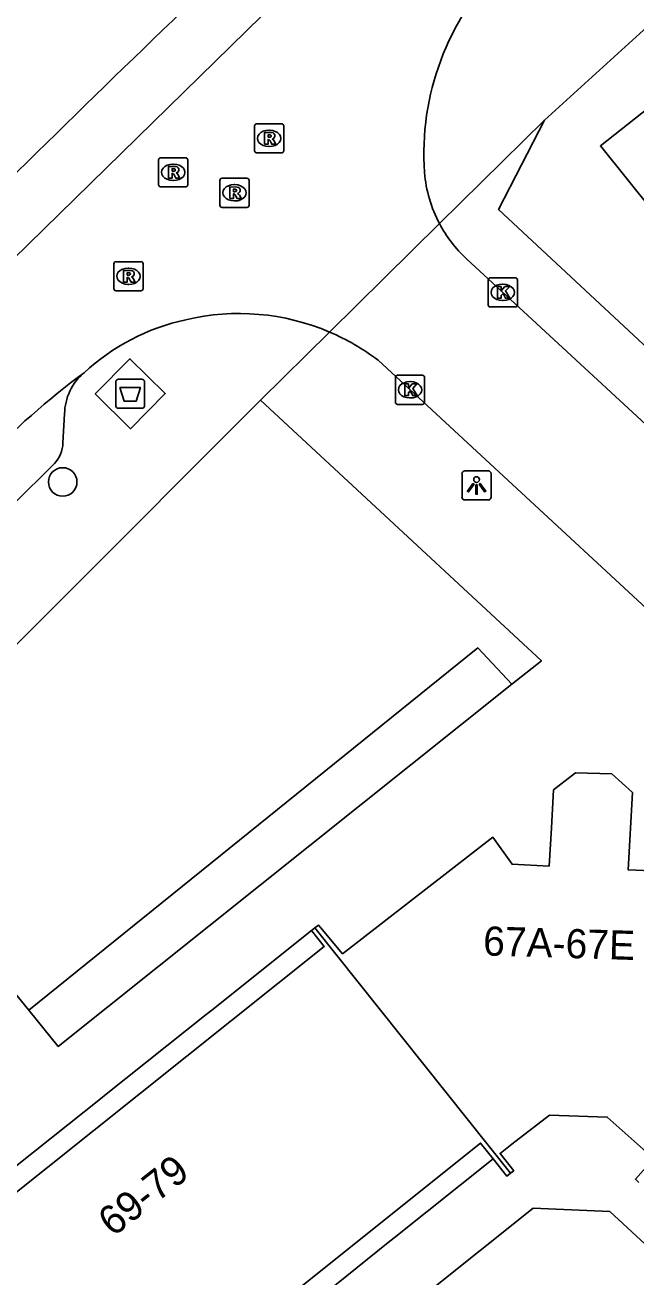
# Model space of a CAD drawing. Extents: x 159040 to 160094, y 381214 to 382518.
# Drawn here: x 159711.7 to 159732.63, y 381862.01 to 381904.94 of the extents above; entities that cross this region are included whole.
import ezdxf

# ---------------------------------------------------------------- set-up
doc = ezdxf.new("R2010")
doc.units = 0
for name, color, linetype in [('IMGEO_Afval_apart_plaats', 7, 'Continuous'), ('IMGEO_Boom', 7, 'Continuous'), ('IMGEO_Haag', 7, 'Continuous'), ('IMGEO_Kolk', 7, 'Continuous'), ('IMGEO_Lichtpunt', 7, 'Continuous'), ('IMGEO_Pand', 7, 'Continuous'), ('IMGEO_Pand_nummerreeks', 7, 'Continuous'), ('IMGEO_Pand_overbouw', 7, 'Continuous'), ('IMGEO_Rijbaan_lokaal_open', 7, 'Continuous'), ('IMGEO_Rioolput', 7, 'Continuous'), ('IMGEO_Voetpad_gesloten', 7, 'Continuous'), ('IMGEO_Voetpad_open', 7, 'Continuous')]:
    doc.layers.add(name, color=color, linetype=linetype)

msp = doc.modelspace()

# ---------------------------------------------------------------- linework, layer by layer
at = {"layer": 'IMGEO_Afval_apart_plaats'}
for p, q in [((159714.807, 381891.897), (159714.807, 381892.697)), ((159714.807, 381892.697), (159714.807, 381891.897)), ((159714.907, 381892.797), (159715.697, 381892.797)), ((159715.697, 381892.797), (159714.907, 381892.797)), ((159715.797, 381892.697), (159715.797, 381891.897)), ((159715.797, 381891.897), (159715.797, 381892.697)), ((159715.697, 381891.797), (159714.907, 381891.797)), ((159714.907, 381891.797), (159715.697, 381891.797))]:
    msp.add_line(p, q, dxfattribs=at)
msp.add_lwpolyline([(159714.95, 381892.511), (159715.654, 381892.511), (159715.505, 381892.041), (159715.099, 381892.041), (159714.95, 381892.511)], dxfattribs=at)
for centre, start, end in [((159714.907, 381892.697), 90, 180), ((159714.907, 381892.697), 90, 180), ((159715.697, 381892.697), 0, 90), ((159715.697, 381892.697), 360, 90), ((159714.907, 381891.897), 180, 270), ((159714.907, 381891.897), 180, 270), ((159715.697, 381891.897), 270, 0), ((159715.697, 381891.897), 270, 0)]:
    msp.add_arc(centre, 0.1, start, end, dxfattribs=at)
at = {"layer": 'IMGEO_Boom'}
msp.add_circle((159712.989, 381889.272), 0.489, dxfattribs=at)
at = {"layer": 'IMGEO_Haag'}
msp.add_lwpolyline([(159711.824, 381871.157), (159727.219, 381883.583), (159728.384, 381882.337)], dxfattribs=at)
at = {"layer": 'IMGEO_Kolk'}
for p, q in [((159727.571, 381895.346), (159727.571, 381896.198)), ((159727.646, 381896.272), (159728.498, 381896.272)), ((159728.572, 381896.198), (159728.572, 381895.346)), ((159728.059, 381896.052), (159728.084, 381896.052)), ((159728.498, 381895.272), (159727.646, 381895.272)), ((159728.082, 381895.492), (159728.057, 381895.492)), ((159724.392, 381892.007), (159724.392, 381892.859)), ((159724.467, 381892.933), (159725.319, 381892.933)), ((159724.88, 381892.713), (159724.905, 381892.713)), ((159725.393, 381892.859), (159725.393, 381892.007)), ((159725.319, 381891.933), (159724.467, 381891.933)), ((159724.903, 381892.153), (159724.878, 381892.153))]:
    msp.add_line(p, q, dxfattribs=at)
for points in [[(159727.571, 381895.346), (159727.571, 381896.198)], [(159727.646, 381896.272), (159728.498, 381896.272)], [(159728.572, 381896.198), (159728.572, 381895.346)], [(159727.892, 381895.972), (159728.015, 381895.972), (159728.015, 381895.821), (159728.145, 381895.972), (159728.309, 381895.972), (159728.163, 381895.821), (159728.316, 381895.572), (159728.164, 381895.572), (159728.079, 381895.736), (159728.015, 381895.669), (159728.015, 381895.572), (159727.892, 381895.572), (159727.892, 381895.972)], [(159728.498, 381895.272), (159727.646, 381895.272)], [(159724.392, 381892.007), (159724.392, 381892.859)], [(159724.467, 381892.933), (159725.319, 381892.933)], [(159725.393, 381892.859), (159725.393, 381892.007)], [(159724.713, 381892.633), (159724.836, 381892.633), (159724.836, 381892.482), (159724.966, 381892.633), (159725.13, 381892.633), (159724.984, 381892.482), (159725.137, 381892.233), (159724.985, 381892.233), (159724.9, 381892.397), (159724.836, 381892.33), (159724.836, 381892.233), (159724.713, 381892.233), (159724.713, 381892.633)], [(159725.319, 381891.933), (159724.467, 381891.933)]]:
    msp.add_lwpolyline(points, dxfattribs=at)
for centre, start, end in [((159727.648, 381896.196), 91.552, 178.448), ((159727.648, 381896.196), 91.552, 178.448), ((159728.496, 381896.196), 1.552, 88.448), ((159728.496, 381896.196), 1.552, 88.448), ((159727.648, 381895.348), 181.552, 268.448), ((159727.648, 381895.348), 181.552, 268.448), ((159728.496, 381895.348), 271.552, 358.448), ((159728.496, 381895.348), 271.552, 358.448), ((159724.469, 381892.857), 91.552, 178.448), ((159724.469, 381892.857), 91.552, 178.448), ((159725.317, 381892.857), 1.552, 88.448), ((159725.317, 381892.857), 1.552, 88.448), ((159724.469, 381892.009), 181.552, 268.448), ((159724.469, 381892.009), 181.552, 268.448), ((159725.317, 381892.009), 271.552, 358.448), ((159725.317, 381892.009), 271.552, 358.448)]:
    msp.add_arc(centre, 0.0765, start, end, dxfattribs=at)
for centre, major_axis, ratio, start_param, end_param in [((159728.058, 381895.772), (-0.387, 0.002), 0.722429, 4.712389, 7.853982), ((159728.083, 381895.772), (-0.39, 0.002), 0.717154, 1.570796, 4.712389), ((159724.879, 381892.433), (-0.387, 0.002), 0.722429, 4.712389, 7.853982), ((159724.904, 381892.433), (-0.39, 0.002), 0.717154, 1.570796, 4.712389)]:
    msp.add_ellipse(centre, major_axis=major_axis, ratio=ratio, start_param=start_param, end_param=end_param, dxfattribs=at)
at = {"layer": 'IMGEO_Lichtpunt'}
for p, q in [((159726.674, 381889.555), (159726.674, 381888.748)), ((159726.674, 381889.555), (159726.674, 381888.748)), ((159727.576, 381889.65), (159726.768, 381889.65)), ((159727.576, 381889.65), (159726.768, 381889.65)), ((159727.67, 381888.748), (159727.67, 381889.555)), ((159727.67, 381888.748), (159727.67, 381889.555)), ((159726.768, 381888.654), (159727.576, 381888.654)), ((159726.768, 381888.654), (159727.576, 381888.654))]:
    msp.add_line(p, q, dxfattribs=at)
for points in [[(159727.048, 381889.219), (159727.087, 381889.191), (159726.899, 381888.929), (159726.861, 381888.956), (159727.048, 381889.219)], [(159727.15, 381889.171), (159727.197, 381889.171), (159727.197, 381888.849), (159727.15, 381888.849), (159727.15, 381889.171)], [(159727.26, 381889.191), (159727.298, 381889.218), (159727.485, 381888.956), (159727.446, 381888.928), (159727.26, 381889.191)]]:
    msp.add_lwpolyline(points, dxfattribs=at)
msp.add_circle((159727.173, 381889.353), 0.0994, dxfattribs=at)
for centre, start, end in [((159726.768, 381889.555), 90, 180), ((159726.768, 381889.555), 90, 180), ((159727.576, 381889.555), 0, 90), ((159727.576, 381889.555), 0, 90), ((159726.768, 381888.748), 180, 270), ((159726.768, 381888.748), 180, 270), ((159727.576, 381888.748), 270, 0), ((159727.576, 381888.748), 270, 360)]:
    msp.add_arc(centre, 0.0946, start, end, dxfattribs=at)
at = {"layer": 'IMGEO_Pand'}
for points in [[(159734.469, 381876.829), (159733.667, 381875.913), (159732.367, 381875.976), (159732.521, 381878.623), (159731.811, 381879.259), (159730.567, 381879.294), (159729.812, 381878.711), (159729.737, 381877.417), (159729.66, 381876.101), (159728.387, 381876.163), (159727.73, 381877.087), (159722.58, 381873.093), (159721.823, 381873.992), (159721.752, 381874.076), (159721.632, 381873.983)], [(159721.632, 381873.983), (159721.518, 381873.896), (159721.948, 381873.339), (159707.762, 381862.012)], [(159721.632, 381873.983), (159728.339, 381865.566)], [(159732.735, 381865.256), (159732.614, 381865.363), (159733.236, 381866.067), (159732.877, 381866.391), (159731.65, 381867.494), (159729.668, 381867.562), (159728.384, 381866.564), (159727.977, 381866.247), (159728.449, 381865.654), (159728.339, 381865.566)], [(159728.339, 381865.566), (159728.215, 381865.467), (159727.738, 381866.065), (159727.31, 381866.603), (159721.033, 381861.58), (159719.36, 381860.242), (159713.145, 381855.268), (159713.585, 381854.718), (159714.179, 381853.975), (159714.07, 381853.886)]]:
    msp.add_lwpolyline(points, dxfattribs=at)
at = {"layer": 'IMGEO_Pand_overbouw'}
for points in [[(159707.762, 381862.012), (159721.948, 381873.339), (159721.518, 381873.896), (159718.097, 381871.164), (159717.909, 381871.014), (159714.481, 381868.278), (159714.288, 381868.123), (159710.871, 381865.396), (159710.674, 381865.239), (159707.341, 381862.578), (159707.33, 381862.569), (159707.483, 381862.371)], [(159727.738, 381866.065), (159727.31, 381866.603), (159721.033, 381861.58), (159721.31, 381861.235), (159721.466, 381861.04), (159721.663, 381861.197), (159724.148, 381863.189), (159724.349, 381863.35)]]:
    msp.add_lwpolyline(points, close=True, dxfattribs=at)
at = {"layer": 'IMGEO_Rijbaan_lokaal_open'}
for points in [[(159734.748, 381919.266), (159721.416, 381906.835), (159704.334, 381890.107)], [(159722.136, 381894.413), (159725.903, 381898.13)], [(159738.817, 381885.832), (159726.824, 381896.926)], [(159723.801, 381893.444), (159745.268, 381873.571)]]:
    msp.add_lwpolyline(points, dxfattribs=at)
for centre, radius, start, end in [((159734.563, 381900.518), 9.197, 135.1668, 183.9559), ((159729.935, 381900.267), 4.563, 184.8231, 207.9206), ((159729.914, 381900.244), 4.534, 207.7901, 227.0382), ((159718.798, 381887.53), 7.477, 102.2484, 132.7573), ((159719.03, 381887.15), 7.899, 66.849, 103.308), ((159718.993, 381887.098), 7.961, 52.8521, 66.7506), ((159730.743, 381870.139), 28.517, 126.6443, 135.9965)]:
    msp.add_arc(centre, radius, start, end, dxfattribs=at)
at = {"layer": 'IMGEO_Rioolput'}
for p, q in [((159719.564, 381900.628), (159719.564, 381901.48)), ((159719.639, 381901.554), (159720.491, 381901.554)), ((159720.052, 381901.334), (159720.077, 381901.334)), ((159720.565, 381901.48), (159720.565, 381900.628)), ((159720.491, 381900.554), (159719.639, 381900.554)), ((159720.075, 381900.774), (159720.05, 381900.774)), ((159716.275, 381899.465), (159716.275, 381900.317)), ((159716.35, 381900.391), (159717.202, 381900.391)), ((159716.763, 381900.171), (159716.788, 381900.171)), ((159717.276, 381900.317), (159717.276, 381899.465)), ((159716.786, 381899.611), (159716.761, 381899.611)), ((159718.378, 381898.762), (159718.378, 381899.614)), ((159718.453, 381899.688), (159719.305, 381899.688)), ((159719.379, 381899.614), (159719.379, 381898.762)), ((159717.202, 381899.391), (159716.35, 381899.391)), ((159718.866, 381899.468), (159718.891, 381899.468)), ((159719.305, 381898.688), (159718.453, 381898.688)), ((159718.889, 381898.908), (159718.864, 381898.908)), ((159714.741, 381895.9), (159714.741, 381896.752)), ((159714.816, 381896.826), (159715.668, 381896.826)), ((159715.229, 381896.606), (159715.254, 381896.606)), ((159715.742, 381896.752), (159715.742, 381895.9)), ((159715.668, 381895.826), (159714.816, 381895.826)), ((159715.252, 381896.046), (159715.227, 381896.046))]:
    msp.add_line(p, q, dxfattribs=at)
for points in [[(159719.564, 381900.628), (159719.564, 381901.48)], [(159719.639, 381901.554), (159720.491, 381901.554)], [(159720.565, 381901.48), (159720.565, 381900.628)], [(159720.153, 381901.252), (159719.901, 381901.254), (159719.901, 381900.854)], [(159719.901, 381900.854), (159720.025, 381900.854), (159720.025, 381901.016), (159720.036, 381901.016)], [(159720.079, 381901.173), (159720.025, 381901.173), (159720.025, 381901.092)], [(159720.025, 381901.092), (159720.077, 381901.092)], [(159720.083, 381900.987), (159720.154, 381900.854), (159720.294, 381900.854), (159720.229, 381900.98)], [(159720.491, 381900.554), (159719.639, 381900.554)], [(159716.275, 381899.465), (159716.275, 381900.317)], [(159716.35, 381900.391), (159717.202, 381900.391)], [(159716.864, 381900.089), (159716.612, 381900.091), (159716.612, 381899.691)], [(159716.79, 381900.01), (159716.736, 381900.01), (159716.736, 381899.929)], [(159717.276, 381900.317), (159717.276, 381899.465)], [(159716.612, 381899.691), (159716.736, 381899.691), (159716.736, 381899.853), (159716.747, 381899.853)], [(159716.736, 381899.929), (159716.788, 381899.929)], [(159716.794, 381899.824), (159716.865, 381899.691), (159717.005, 381899.691), (159716.94, 381899.817)], [(159718.378, 381898.762), (159718.378, 381899.614)], [(159718.453, 381899.688), (159719.305, 381899.688)], [(159719.379, 381899.614), (159719.379, 381898.762)], [(159717.202, 381899.391), (159716.35, 381899.391)], [(159718.967, 381899.386), (159718.715, 381899.388), (159718.715, 381898.988)], [(159718.715, 381898.988), (159718.839, 381898.988), (159718.839, 381899.15), (159718.85, 381899.15)], [(159718.893, 381899.307), (159718.839, 381899.307), (159718.839, 381899.226)], [(159718.839, 381899.226), (159718.891, 381899.226)], [(159718.897, 381899.121), (159718.968, 381898.988), (159719.108, 381898.988), (159719.043, 381899.114)], [(159719.305, 381898.688), (159718.453, 381898.688)], [(159714.741, 381895.9), (159714.741, 381896.752)], [(159714.816, 381896.826), (159715.668, 381896.826)], [(159715.742, 381896.752), (159715.742, 381895.9)], [(159715.33, 381896.524), (159715.078, 381896.526), (159715.078, 381896.126)], [(159715.078, 381896.126), (159715.202, 381896.126), (159715.202, 381896.288), (159715.213, 381896.288)], [(159715.256, 381896.445), (159715.202, 381896.445), (159715.202, 381896.364)], [(159715.202, 381896.364), (159715.254, 381896.364)], [(159715.26, 381896.259), (159715.331, 381896.126), (159715.471, 381896.126), (159715.406, 381896.252)], [(159715.668, 381895.826), (159714.816, 381895.826)]]:
    msp.add_lwpolyline(points, dxfattribs=at)
for centre, radius, start, end in [((159719.641, 381901.478), 0.0765, 91.552, 178.448), ((159719.641, 381901.478), 0.0765, 91.552, 178.448), ((159720.489, 381901.478), 0.0765, 1.552, 88.448), ((159720.489, 381901.478), 0.0765, 1.552, 88.448), ((159720.035, 381900.963), 0.0533, 26.0293, 88.6989), ((159720.061, 381901.281), 0.19, 274.7715, 282.9687), ((159720.085, 381901.077), 0.0964, 77.0061, 93.1865), ((159720.099, 381901.134), 0.0378, 276.6634, 79.6772), ((159720.152, 381901.142), 0.109, 350.3612, 89.416), ((159720.15, 381901.142), 0.112, 277.5842, 350.9817), ((159720.134, 381900.927), 0.108, 29.5134, 73.7905), ((159719.641, 381900.63), 0.0765, 181.552, 268.448), ((159719.641, 381900.63), 0.0765, 181.552, 268.448), ((159720.489, 381900.63), 0.0765, 271.552, 358.448), ((159720.489, 381900.63), 0.0765, 271.552, 358.448), ((159716.352, 381900.315), 0.0765, 91.552, 178.448), ((159716.352, 381900.315), 0.0765, 91.552, 178.448), ((159716.796, 381899.914), 0.0964, 77.0061, 93.1865), ((159716.81, 381899.971), 0.0378, 276.6634, 79.6772), ((159716.863, 381899.979), 0.109, 350.3612, 89.416), ((159717.2, 381900.315), 0.0765, 1.552, 88.448), ((159717.2, 381900.315), 0.0765, 1.552, 88.448), ((159716.746, 381899.8), 0.0533, 26.0293, 88.6989), ((159716.772, 381900.118), 0.19, 274.7715, 282.9687), ((159716.861, 381899.979), 0.112, 277.5842, 350.9817), ((159716.845, 381899.764), 0.108, 29.5134, 73.7905), ((159718.455, 381899.612), 0.0765, 91.552, 178.448), ((159718.455, 381899.612), 0.0765, 91.552, 178.448), ((159719.303, 381899.612), 0.0765, 1.552, 88.448), ((159719.303, 381899.612), 0.0765, 1.552, 88.448), ((159716.352, 381899.467), 0.0765, 181.552, 268.448), ((159716.352, 381899.467), 0.0765, 181.552, 268.448), ((159717.2, 381899.467), 0.0765, 271.552, 358.448), ((159717.2, 381899.467), 0.0765, 271.552, 358.448), ((159718.849, 381899.097), 0.0533, 26.0293, 88.6989), ((159718.875, 381899.415), 0.19, 274.7715, 282.9687), ((159718.899, 381899.211), 0.0964, 77.0061, 93.1865), ((159718.913, 381899.268), 0.0378, 276.6634, 79.6772), ((159718.966, 381899.276), 0.109, 350.3612, 89.416), ((159718.964, 381899.276), 0.112, 277.5842, 350.9817), ((159718.948, 381899.061), 0.108, 29.5134, 73.7905), ((159718.455, 381898.764), 0.0765, 181.552, 268.448), ((159718.455, 381898.764), 0.0765, 181.552, 268.448), ((159719.303, 381898.764), 0.0765, 271.552, 358.448), ((159719.303, 381898.764), 0.0765, 271.552, 358.448), ((159714.818, 381896.75), 0.0765, 91.552, 178.448), ((159714.818, 381896.75), 0.0765, 91.552, 178.448), ((159715.666, 381896.75), 0.0765, 1.552, 88.448), ((159715.666, 381896.75), 0.0765, 1.552, 88.448), ((159715.212, 381896.235), 0.0533, 26.0293, 88.6989), ((159715.238, 381896.553), 0.19, 274.7715, 282.9687), ((159715.262, 381896.349), 0.0964, 77.0061, 93.1865), ((159715.276, 381896.406), 0.0378, 276.6634, 79.6772), ((159715.329, 381896.414), 0.109, 350.3612, 89.416), ((159715.327, 381896.414), 0.112, 277.5842, 350.9817), ((159715.311, 381896.199), 0.108, 29.5134, 73.7905), ((159714.818, 381895.902), 0.0765, 181.552, 268.448), ((159714.818, 381895.902), 0.0765, 181.552, 268.448), ((159715.666, 381895.902), 0.0765, 271.552, 358.448), ((159715.666, 381895.902), 0.0765, 271.552, 358.448)]:
    msp.add_arc(centre, radius, start, end, dxfattribs=at)
for centre, major_axis, ratio, start_param, end_param in [((159720.051, 381901.054), (-0.387, 0.002), 0.722429, 4.712389, 7.853982), ((159720.076, 381901.054), (-0.39, 0.002), 0.717154, 1.570796, 4.712389), ((159716.762, 381899.891), (-0.387, 0.002), 0.722429, 4.712389, 7.853982), ((159716.787, 381899.891), (-0.39, 0.002), 0.717154, 1.570796, 4.712389), ((159718.865, 381899.188), (-0.387, 0.002), 0.722429, 4.712389, 7.853982), ((159718.89, 381899.188), (-0.39, 0.002), 0.717154, 1.570796, 4.712389), ((159715.228, 381896.326), (-0.387, 0.002), 0.722429, 4.712389, 7.853982), ((159715.253, 381896.326), (-0.39, 0.002), 0.717154, 1.570796, 4.712389)]:
    msp.add_ellipse(centre, major_axis=major_axis, ratio=ratio, start_param=start_param, end_param=end_param, dxfattribs=at)
at = {"layer": 'IMGEO_Voetpad_gesloten'}
for points in [[(159714.102, 381892.29), (159715.291, 381893.497), (159716.502, 381892.304), (159715.313, 381891.097), (159714.102, 381892.29)], [(159759.91, 381838.199), (159731.741, 381864.255), (159729.111, 381864.371), (159711.176, 381850.04), (159696.84, 381838.731), (159696.855, 381838.62), (159689.775, 381833.087), (159686.085, 381829.985)]]:
    msp.add_lwpolyline(points, dxfattribs=at)
at = {"layer": 'IMGEO_Voetpad_open'}
for points in [[(159735.282, 381906.952), (159736.807, 381905.056), (159731.419, 381900.793), (159740.485, 381889.477), (159738.999, 381888.305), (159727.928, 381898.616), (159729.499, 381901.679)], [(159729.499, 381901.679), (159735.282, 381906.952)], [(159725.903, 381898.13), (159729.499, 381901.679)], [(159719.769, 381892.076), (159722.136, 381894.413)], [(159706.005, 381878.291), (159719.769, 381892.076)], [(159719.769, 381892.076), (159729.394, 381883.143), (159728.384, 381882.337)], [(159713.053, 381891.606), (159712.997, 381890.611)], [(159712.706, 381889.901), (159711.279, 381888.487), (159697.132, 381874.129)], [(159728.384, 381882.337), (159712.834, 381869.918), (159711.824, 381871.157)], [(159711.824, 381871.157), (159706.005, 381878.291)]]:
    msp.add_lwpolyline(points, dxfattribs=at)
for centre, radius, start, end in [((160268.192, 381333.437), 794.276, 132.527832, 134.671689), ((159714.937, 381891.58), 1.884, 130.1582, 179.2017), ((159711.936, 381890.631), 1.061, 316.5214, 358.9051)]:
    msp.add_arc(centre, radius, start, end, dxfattribs=at)

# ---------------------------------------------------------------- texts
at = {"layer": 'IMGEO_Pand_nummerreeks'}
for s, rotation, p in [('67A-67E', 358.2342, (159727.387, 381873.039)), ('69-79', 38.3351, (159714.715, 381863.364))]:
    msp.add_text(s, height=1, rotation=rotation, dxfattribs=at).set_placement(p)

doc.saveas('drawing.dxf')
